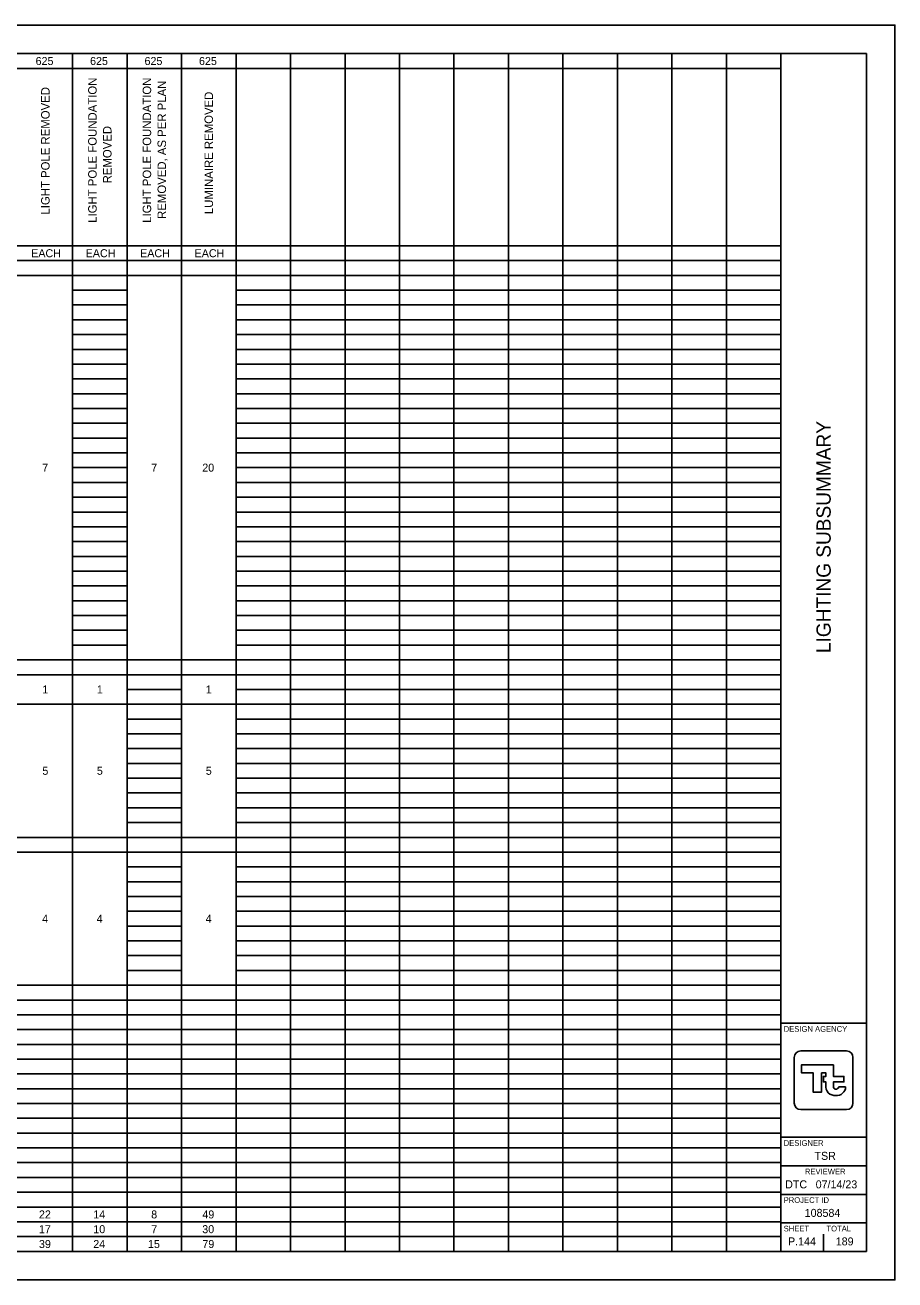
# Model space of a CAD drawing. Extents: x 0 to 34, y 0 to 22.
# Drawn here: x 18.75 to 34, y 0 to 22 of the extents above; entities that cross this region are included whole.
import ezdxf

# ---------------------------------------------------------------- set-up
doc = ezdxf.new("R2010")
doc.units = 0
for name, color, linetype in [('Default', 7, 'Continuous'), ('SH_Border', 7, 'Continuous'), ('SH_Cut_Line', 7, 'Continuous'), ('SH_Data', 7, 'Continuous')]:
    doc.layers.add(name, color=color, linetype=linetype)

msp = doc.modelspace()

# ---------------------------------------------------------------- linework, layer by layer
at = {"layer": 'Default'}
for p, q in [((1.5, 21.5), (32, 21.5)), ((19.583, 21.5), (19.583, 1.278)), ((20.538, 21.5), (20.538, 1.278)), ((21.493, 21.5), (21.493, 1.278)), ((22.449, 21.5), (22.449, 1.278)), ((23.404, 21.5), (23.404, 1.278)), ((24.359, 21.5), (24.359, 1.278)), ((25.314, 21.5), (25.314, 1.278)), ((26.269, 21.5), (26.269, 1.278)), ((27.224, 21.5), (27.224, 1.278)), ((28.179, 21.5), (28.179, 1.278)), ((29.135, 21.5), (29.135, 1.278)), ((30.09, 21.5), (30.09, 1.278)), ((31.045, 21.5), (31.045, 1.278)), ((32, 21.5), (32, 1.278)), ((13.852, 21.241), (32, 21.241)), ((13.852, 18.13), (32, 18.13)), ((1.5, 17.87), (32, 17.87)), ((1.5, 17.611), (32, 17.611)), ((19.583, 17.352), (20.538, 17.352)), ((22.449, 17.352), (32, 17.352)), ((19.583, 17.093), (20.538, 17.093)), ((22.449, 17.093), (32, 17.093)), ((19.583, 16.833), (20.538, 16.833)), ((22.449, 16.833), (32, 16.833)), ((19.583, 16.574), (20.538, 16.574)), ((22.449, 16.574), (32, 16.574)), ((19.583, 16.315), (20.538, 16.315)), ((22.449, 16.315), (32, 16.315)), ((19.583, 16.056), (20.538, 16.056)), ((22.449, 16.056), (32, 16.056)), ((19.583, 15.796), (20.538, 15.796)), ((22.449, 15.796), (32, 15.796)), ((19.583, 15.537), (20.538, 15.537)), ((22.449, 15.537), (32, 15.537)), ((19.583, 15.278), (20.538, 15.278)), ((22.449, 15.278), (32, 15.278)), ((19.583, 15.019), (20.538, 15.019)), ((22.449, 15.019), (32, 15.019)), ((19.583, 14.759), (20.538, 14.759)), ((22.449, 14.759), (32, 14.759)), ((19.583, 14.5), (20.538, 14.5)), ((22.449, 14.5), (32, 14.5)), ((19.583, 14.241), (20.538, 14.241)), ((22.449, 14.241), (32, 14.241)), ((19.583, 13.981), (20.538, 13.981)), ((22.449, 13.981), (32, 13.981)), ((19.583, 13.722), (20.538, 13.722)), ((22.449, 13.722), (32, 13.722)), ((19.583, 13.463), (20.538, 13.463)), ((22.449, 13.463), (32, 13.463)), ((19.583, 13.204), (20.538, 13.204)), ((22.449, 13.204), (32, 13.204)), ((19.583, 12.944), (20.538, 12.944)), ((22.449, 12.944), (32, 12.944)), ((19.583, 12.685), (20.538, 12.685)), ((22.449, 12.685), (32, 12.685)), ((19.583, 12.426), (20.538, 12.426)), ((22.449, 12.426), (32, 12.426)), ((19.583, 12.167), (20.538, 12.167)), ((22.449, 12.167), (32, 12.167)), ((19.583, 11.907), (20.538, 11.907)), ((22.449, 11.907), (32, 11.907)), ((19.583, 11.648), (20.538, 11.648)), ((22.449, 11.648), (32, 11.648)), ((19.583, 11.389), (20.538, 11.389)), ((22.449, 11.389), (32, 11.389)), ((19.583, 11.13), (20.538, 11.13)), ((22.449, 11.13), (32, 11.13)), ((1.5, 10.87), (32, 10.87)), ((1.5, 10.611), (32, 10.611)), ((20.538, 10.352), (21.493, 10.352)), ((22.449, 10.352), (32, 10.352)), ((1.5, 10.093), (32, 10.093)), ((20.538, 9.833), (21.493, 9.833)), ((22.449, 9.833), (32, 9.833)), ((20.538, 9.574), (21.493, 9.574)), ((22.449, 9.574), (32, 9.574)), ((20.538, 9.315), (21.493, 9.315)), ((22.449, 9.315), (32, 9.315)), ((20.538, 9.056), (21.493, 9.056)), ((22.449, 9.056), (32, 9.056)), ((20.538, 8.796), (21.493, 8.796)), ((22.449, 8.796), (32, 8.796)), ((20.538, 8.537), (21.493, 8.537)), ((22.449, 8.537), (32, 8.537)), ((20.538, 8.278), (21.493, 8.278)), ((22.449, 8.278), (32, 8.278)), ((20.538, 8.019), (21.493, 8.019)), ((22.449, 8.019), (32, 8.019)), ((1.5, 7.759), (32, 7.759)), ((1.5, 7.5), (32, 7.5)), ((20.538, 7.241), (21.493, 7.241)), ((22.449, 7.241), (32, 7.241)), ((20.538, 6.981), (21.493, 6.981)), ((22.449, 6.981), (32, 6.981)), ((20.538, 6.722), (21.493, 6.722)), ((22.449, 6.722), (32, 6.722)), ((20.538, 6.463), (21.493, 6.463)), ((22.449, 6.463), (32, 6.463)), ((20.538, 6.204), (21.493, 6.204)), ((22.449, 6.204), (32, 6.204)), ((20.538, 5.944), (21.493, 5.944)), ((22.449, 5.944), (32, 5.944)), ((20.538, 5.685), (21.493, 5.685)), ((22.449, 5.685), (32, 5.685)), ((20.538, 5.426), (21.493, 5.426)), ((22.449, 5.426), (32, 5.426)), ((1.5, 5.167), (32, 5.167)), ((1.5, 4.907), (32, 4.907)), ((1.5, 4.648), (32, 4.648)), ((1.5, 4.389), (32, 4.389)), ((1.5, 4.13), (32, 4.13)), ((1.5, 3.87), (32, 3.87)), ((1.5, 3.611), (32, 3.611)), ((1.5, 3.352), (32, 3.352)), ((1.5, 3.093), (32, 3.093)), ((1.5, 2.833), (32, 2.833)), ((1.5, 2.574), (32, 2.574)), ((1.5, 2.315), (32, 2.315)), ((1.5, 2.056), (32, 2.056)), ((1.5, 1.796), (32, 1.796)), ((1.5, 1.537), (32, 1.537)), ((1.5, 1.278), (32, 1.278)), ((19.583, 1.278), (19.583, 0.5)), ((20.538, 1.278), (20.538, 0.5)), ((21.493, 1.278), (21.493, 0.5)), ((22.449, 1.278), (22.449, 0.5)), ((23.404, 1.278), (23.404, 0.5)), ((24.359, 1.278), (24.359, 0.5)), ((25.314, 1.278), (25.314, 0.5)), ((26.269, 1.278), (26.269, 0.5)), ((27.224, 1.278), (27.224, 0.5)), ((28.179, 1.278), (28.179, 0.5)), ((29.135, 1.278), (29.135, 0.5)), ((30.09, 1.278), (30.09, 0.5)), ((31.045, 1.278), (31.045, 0.5)), ((32, 1.278), (32, 0.5)), ((1.5, 1.019), (32, 1.019)), ((1.5, 0.759), (32, 0.759)), ((13.852, 0.5), (32, 0.5))]:
    msp.add_line(p, q, dxfattribs=at)
at = {"layer": 'SH_Border'}
for p, q in [((32, 0.5), (32, 21.5)), ((32, 4.5), (33.5, 4.5)), ((32, 2.5), (33.5, 2.5)), ((32, 2), (33.5, 2)), ((32, 1.5), (33.5, 1.5)), ((32, 1), (33.5, 1))]:
    msp.add_line(p, q, dxfattribs=at)
msp.add_lwpolyline([(1.5, 21.5), (33.5, 21.5), (33.5, 0.5), (1.5, 0.5)], close=True, dxfattribs=at)
at = {"layer": 'SH_Cut_Line'}
msp.add_lwpolyline([(0, 0), (34, 0), (34, 22), (0, 22)], close=True, dxfattribs=at)
at = {"layer": 'SH_Data'}
for p, q in [((32.75, 3.5), (32.75, 3.5)), ((32.791, 3.415), (32.791, 3.415)), ((33.136, 3.385), (33.015, 3.385)), ((32.375, 0.675), (32.375, 0.675)), ((32.75, 0.5), (32.75, 0.8))]:
    msp.add_line(p, q, dxfattribs=at)
for points in [[(32.348, 4.014), (33.152, 4.014)], [(32.236, 3.099), (32.236, 3.901)], [(32.922, 3.399), (32.922, 3.47), (33.107, 3.47), (33.107, 3.568), (32.922, 3.568), (32.922, 3.768), (32.361, 3.768), (32.361, 3.632), (32.566, 3.632), (32.566, 3.294), (32.715, 3.294), (32.715, 3.63), (32.79, 3.63), (32.79, 3.568), (32.748, 3.568), (32.748, 3.47), (32.79, 3.47), (32.79, 3.415), (32.791, 3.415)], [(33.264, 3.901), (33.264, 3.099)], [(33.152, 2.986), (32.348, 2.986)]]:
    msp.add_lwpolyline(points, dxfattribs=at)
for centre, radius, start, end in [((32.348, 3.901), 0.113, 90, 180), ((33.152, 3.901), 0.113, 360, 90), ((32.949, 3.392), 0.16, 171.8856, 274.8323), ((32.968, 3.392), 0.0473, 171.8856, 350.9243), ((32.976, 3.392), 0.16, 265.1677, 357.3201), ((32.348, 3.099), 0.113, 180, 270), ((33.152, 3.099), 0.113, 270, 360)]:
    msp.add_arc(centre, radius, start, end, dxfattribs=at)

# ---------------------------------------------------------------- texts
at = {"layer": 'Default'}
for s, height, p in [('625', 0.1403, (18.934, 21.3)), ('625', 0.1403, (19.889, 21.3)), ('625', 0.1403, (20.844, 21.3)), ('625', 0.1403, (21.799, 21.3)), ('EACH', 0.1403, (18.857, 17.93)), ('EACH', 0.1403, (19.812, 17.93)), ('EACH', 0.1403, (20.767, 17.93)), ('EACH', 0.1403, (21.722, 17.93)), ('7', 0.14, (19.051, 14.171)), ('7', 0.14, (20.962, 14.171)), ('20', 0.1403, (21.856, 14.171)), ('1', 0.14, (19.052, 10.282)), ('1', 0.14, (20.008, 10.282)), ('1', 0.14, (21.918, 10.282)), ('5', 0.14, (19.053, 8.856)), ('5', 0.14, (20.008, 8.856)), ('5', 0.14, (21.918, 8.856)), ('4', 0.14, (19.049, 6.263)), ('4', 0.14, (20.005, 6.263)), ('4', 0.14, (21.915, 6.263)), ('22', 0.1403, (18.993, 1.078)), ('14', 0.1403, (19.945, 1.078)), ('8', 0.14, (20.961, 1.078)), ('49', 0.1403, (21.858, 1.078)), ('17', 0.1403, (18.992, 0.819)), ('10', 0.1403, (19.946, 0.819)), ('7', 0.14, (20.962, 0.819)), ('30', 0.1403, (21.856, 0.819)), ('39', 0.1403, (18.993, 0.559)), ('24', 0.1403, (19.945, 0.559)), ('15', 0.1403, (20.904, 0.559)), ('79', 0.1403, (21.858, 0.559))]:
    msp.add_text(s, height=height, dxfattribs=at).set_placement(p)
for s, height, p in [('LIGHT POLE REMOVED', 0.14894, (19.18, 18.678)), ('LIGHT POLE FOUNDATION ', 0.14894, (20.005, 18.534)), ('LIGHT POLE FOUNDATION ', 0.14894, (20.96, 18.534)), ('REMOVED, AS PER PLAN', 0.14894, (21.221, 18.602)), ('LUMINAIRE REMOVED', 0.14894, (22.045, 18.686)), ('REMOVED', 0.1489, (20.265, 19.225))]:
    msp.add_text(s, height=height, rotation=90, dxfattribs=at).set_placement(p)
at = {"layer": 'SH_Data'}
msp.add_text('LIGHTING SUBSUMMARY', height=0.25, rotation=90, dxfattribs=at).set_placement((32.875, 10.99))
for s, height, p in [('DESIGN AGENCY', 0.1, (32.05, 4.35)), ('DESIGNER', 0.1, (32.05, 2.35)), ('TSR', 0.14, (32.59, 2.105)), ('REVIEWER', 0.1, (32.422, 1.85)), ('DTC', 0.14, (32.076, 1.605)), ('07/14/23', 0.14, (32.611, 1.605)), ('PROJECT ID', 0.1, (32.05, 1.35)), ('108584', 0.14, (32.418, 1.105)), ('SHEET', 0.1, (32.05, 0.85)), ('TOTAL', 0.1, (32.8, 0.85)), ('P.144', 0.14, (32.126, 0.605)), ('189', 0.14, (32.963, 0.605))]:
    msp.add_text(s, height=height, dxfattribs=at).set_placement(p)

doc.saveas('drawing.dxf')
